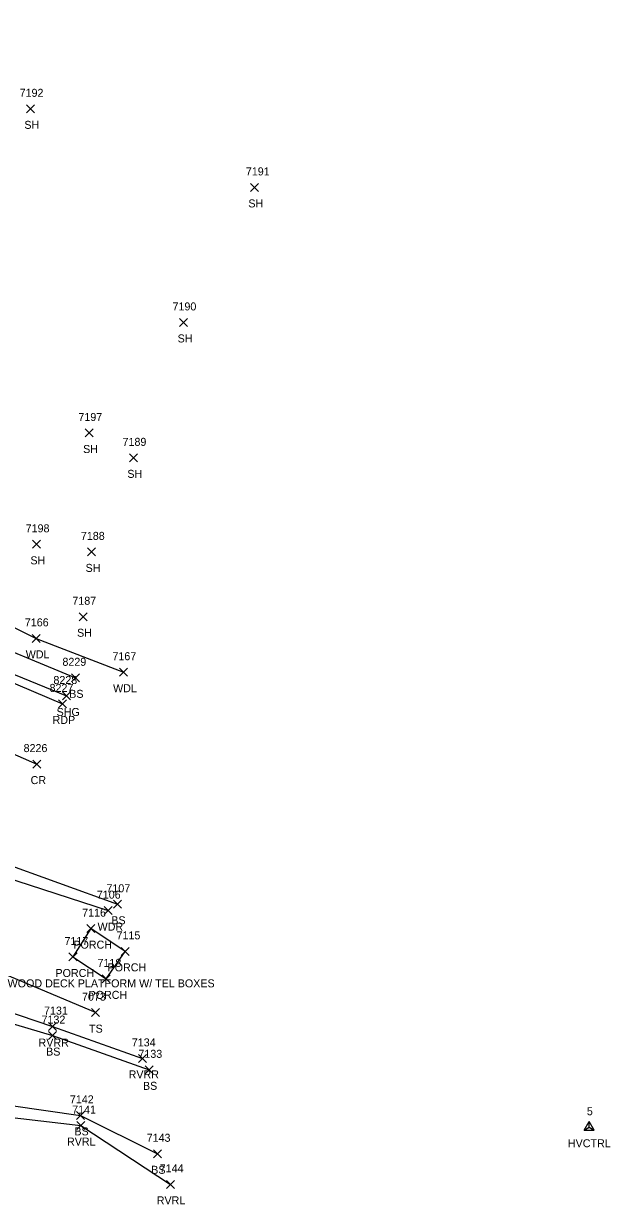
# Model space of a CAD drawing. Extents: x 1588028 to 1589597, y 137576 to 138176.
# Drawn here: x 1589450 to 1589596.6, y 137576.4 to 137871.5 of the extents above; entities that cross this region are included whole.
import ezdxf

# ---------------------------------------------------------------- set-up
doc = ezdxf.new("R2010")
doc.units = 0
for name, color, linetype in [('C_A', 7, 'Continuous'), ('C_I', 7, 'Continuous'), ('CPSM', 7, 'Continuous'), ('L_A', 7, 'Continuous'), ('L_C', 7, 'Continuous'), ('L_I', 7, 'Continuous'), ('L_TIC', 7, 'Continuous'), ('LAWA', 7, 'Continuous'), ('LAWE', 7, 'Continuous'), ('LBF', 7, 'Continuous'), ('LELB', 7, 'Continuous'), ('P_A', 7, 'Continuous'), ('P_I', 7, 'Continuous'), ('P_TIC', 7, 'Continuous'), ('PET', 7, 'Continuous'), ('PRC', 7, 'Continuous'), ('PSU', 7, 'Continuous')]:
    doc.layers.add(name, color=color, linetype=linetype)

msp = doc.modelspace()

# ---------------------------------------------------------------- linework, layer by layer
at = {"layer": 'CPSM'}
for p, q in [((1589590.03, 137594.95), (1589591.28, 137597.12)), ((1589590.03, 137594.95), (1589591.28, 137595.67)), ((1589590.03, 137594.95), (1589592.53, 137594.95)), ((1589592.53, 137594.95), (1589591.28, 137597.12)), ((1589591.28, 137595.67), (1589591.28, 137597.12)), ((1589591.28, 137595.67), (1589591.28, 137595.67)), ((1589591.28, 137595.67), (1589592.53, 137594.95))]:
    msp.add_line(p, q, dxfattribs=at)
at = {"layer": 'L_TIC'}
for points in [[(1589450.71, 137849.18), (1589452.71, 137851.18)], [(1589452.71, 137849.18), (1589450.71, 137851.18)], [(1589506.66, 137829.53), (1589508.66, 137831.53)], [(1589508.66, 137829.53), (1589506.66, 137831.53)], [(1589488.99, 137795.79), (1589490.99, 137797.79)], [(1589490.99, 137795.79), (1589488.99, 137797.79)], [(1589465.39, 137768.16), (1589467.39, 137770.16)], [(1589467.39, 137768.16), (1589465.39, 137770.16)], [(1589476.43, 137761.95), (1589478.43, 137763.95)], [(1589478.43, 137761.95), (1589476.43, 137763.95)], [(1589452.22, 137740.34), (1589454.22, 137742.34)], [(1589454.22, 137740.34), (1589452.22, 137742.34)], [(1589466.01, 137738.45), (1589468.01, 137740.45)], [(1589468.01, 137738.45), (1589466.01, 137740.45)], [(1589463.89, 137722.24), (1589465.89, 137724.24)], [(1589465.89, 137722.24), (1589463.89, 137724.24)], [(1589452.12, 137716.84), (1589454.12, 137718.84)], [(1589454.12, 137716.84), (1589452.12, 137718.84)], [(1589473.94, 137708.38), (1589475.94, 137710.38)], [(1589475.94, 137708.38), (1589473.94, 137710.38)], [(1589461.97, 137706.98), (1589463.97, 137708.98)], [(1589463.97, 137706.98), (1589461.97, 137708.98)], [(1589472.48, 137650.39), (1589474.48, 137652.39)], [(1589474.48, 137650.39), (1589472.48, 137652.39)], [(1589470.13, 137648.8), (1589472.13, 137650.8)], [(1589472.13, 137648.8), (1589470.13, 137650.8)], [(1589465.82, 137644.3), (1589467.82, 137646.3)], [(1589467.82, 137644.3), (1589465.82, 137646.3)], [(1589461.35, 137637.22), (1589463.35, 137639.22)], [(1589463.35, 137637.22), (1589461.35, 137639.22)], [(1589474.36, 137638.63), (1589476.36, 137640.63)], [(1589476.36, 137638.63), (1589474.36, 137640.63)], [(1589469.61, 137631.75), (1589471.61, 137633.75)], [(1589471.61, 137631.75), (1589469.61, 137633.75)], [(1589466.95, 137623.31), (1589468.95, 137625.31)], [(1589468.95, 137623.31), (1589466.95, 137625.31)], [(1589456.23, 137619.82), (1589458.23, 137621.82)], [(1589458.23, 137619.82), (1589456.23, 137621.82)], [(1589456.19, 137617.58), (1589458.19, 137619.58)], [(1589458.19, 137617.58), (1589456.19, 137619.58)], [(1589478.74, 137611.88), (1589480.74, 137613.88)], [(1589480.74, 137611.88), (1589478.74, 137613.88)], [(1589480.39, 137609.02), (1589482.39, 137611.02)], [(1589482.39, 137609.02), (1589480.39, 137611.02)], [(1589463.26, 137597.64), (1589465.26, 137599.64)], [(1589465.26, 137597.64), (1589463.26, 137599.64)], [(1589463.28, 137595.09), (1589465.28, 137597.09)], [(1589465.28, 137595.09), (1589463.28, 137597.09)], [(1589482.45, 137588.04), (1589484.45, 137590.04)], [(1589484.45, 137588.04), (1589482.45, 137590.04)], [(1589485.71, 137580.4), (1589487.71, 137582.4)], [(1589487.71, 137580.4), (1589485.71, 137582.4)]]:
    msp.add_lwpolyline(points, dxfattribs=at)
at = {"layer": 'LAWA'}
for points in [[(1589191.48, 137827.66), (1589208.47, 137821.19), (1589231.01, 137810.22), (1589260.79, 137799.99), (1589288.54, 137790.36), (1589312.49, 137778.55), (1589337.68, 137767.31), (1589356.85, 137760.89), (1589388.23, 137746.7), (1589420.91, 137733.88), (1589453.12, 137717.84), (1589474.94, 137709.38)], [(1589349.24, 137689.61), (1589382.22, 137681.05), (1589414.78, 137667.9), (1589444.95, 137658.35), (1589471.13, 137649.8)]]:
    msp.add_lwpolyline(points, dxfattribs=at)
at = {"layer": 'LAWE'}
for points in [[(1588998.37, 137781.01), (1589022.99, 137780.11), (1589053.11, 137769.29), (1589085.17, 137761.52), (1589118.32, 137748.59), (1589139.23, 137719.4), (1589162.49, 137704.02), (1589194.14, 137678.84), (1589218.55, 137662.87), (1589237.06, 137655.88), (1589274.24, 137640.2), (1589299.98, 137630.61), (1589325.3, 137627.35), (1589364.55, 137614.89), (1589400.15, 137603.63), (1589430.64, 137600.05), (1589464.28, 137596.09), (1589486.71, 137581.4)], [(1589165.8, 137734.64), (1589187.94, 137715.26), (1589212.73, 137704.5), (1589228.51, 137693.02), (1589244.33, 137677.06), (1589269.62, 137665.25), (1589295.65, 137657.92), (1589324.97, 137652.81), (1589365.32, 137641.86), (1589399.41, 137634.7), (1589423.88, 137632.18), (1589457.23, 137620.82), (1589479.74, 137612.88)]]:
    msp.add_lwpolyline(points, dxfattribs=at)
at = {"layer": 'LBF'}
for points in [[(1589475.36, 137639.63), (1589466.82, 137645.3), (1589462.35, 137638.22), (1589470.61, 137632.75)], [(1589470.61, 137632.75), (1589475.36, 137639.63)]]:
    msp.add_lwpolyline(points, dxfattribs=at)
at = {"layer": 'LELB'}
for points in [[(1588992.54, 137792.39), (1589023.3, 137782.03), (1589052.1, 137771.44), (1589084.42, 137763.28), (1589121.54, 137752.14), (1589143.04, 137720.61), (1589163.05, 137704.95), (1589194.58, 137680.14), (1589220, 137665.12), (1589237.76, 137657.31), (1589273.63, 137642.37), (1589300.04, 137631.76), (1589324.52, 137628.67), (1589366.23, 137617.74), (1589400.05, 137606.05), (1589430.12, 137603.56), (1589464.26, 137598.64), (1589483.45, 137589.04)], [(1589357.82, 137751.59), (1589375.51, 137744.43), (1589404.41, 137733.04), (1589436.02, 137719.14), (1589462.97, 137707.98)], [(1589467.95, 137624.31), (1589440.56, 137635.88), (1589398.74, 137645.95), (1589371.69, 137651.72), (1589343.02, 137657.2), (1589343.09, 137676.77), (1589344.49, 137692.63)], [(1589349.04, 137693.04), (1589381.83, 137683.89), (1589416.13, 137670.61), (1589443.9, 137662.06), (1589473.48, 137651.39)], [(1589327.62, 137649.4), (1589364.6, 137640.66), (1589399.91, 137633.14), (1589424.96, 137628.14), (1589457.19, 137618.58), (1589481.39, 137610.02)]]:
    msp.add_lwpolyline(points, dxfattribs=at)
at = {"layer": 'P_TIC'}
for points in [[(1589459.72, 137702.44), (1589461.72, 137704.44)], [(1589461.72, 137702.44), (1589459.72, 137704.44)], [(1589458.76, 137700.46), (1589460.76, 137702.46)], [(1589460.76, 137700.46), (1589458.76, 137702.46)], [(1589452.33, 137685.42), (1589454.33, 137687.42)], [(1589454.33, 137685.42), (1589452.33, 137687.42)]]:
    msp.add_lwpolyline(points, dxfattribs=at)
at = {"layer": 'PET'}
msp.add_lwpolyline([(1588976.42, 137837.98), (1588964.71, 137855.4), (1588953.74, 137871.46), (1588980.82, 137866.91), (1589021.21, 137859.55), (1589054.58, 137852.92), (1589087.36, 137843.77), (1589127.64, 137831.45), (1589150.05, 137824.37), (1589196.14, 137808.72), (1589243.87, 137790.96), (1589276.87, 137778.08), (1589322.25, 137759.62), (1589367.82, 137740.82), (1589401.87, 137726.11), (1589432.81, 137712.85), (1589459.76, 137701.46)], dxfattribs=at)
at = {"layer": 'PRC'}
msp.add_lwpolyline([(1588964.71, 137855.4), (1588980.14, 137852.51), (1589018.19, 137844.35), (1589051.57, 137836.27), (1589092.27, 137825.07), (1589122.68, 137816.23), (1589170.7, 137800.29), (1589190.72, 137793.38), (1589238.44, 137775.62), (1589271.31, 137762.4), (1589315.94, 137744.35), (1589366.22, 137723.58), (1589395.71, 137710.87), (1589428.18, 137697.42), (1589453.33, 137686.42)], dxfattribs=at)
at = {"layer": 'PSU'}
msp.add_lwpolyline([(1589152.74, 137827.96), (1589197.07, 137811.88), (1589244.81, 137793.79), (1589277.33, 137781.11), (1589323.36, 137762.65), (1589353.23, 137749.52), (1589368.68, 137743.62), (1589402.84, 137728.77), (1589433.2, 137714.7), (1589460.72, 137703.44)], dxfattribs=at)

# ---------------------------------------------------------------- texts
at = {"layer": 'C_A'}
msp.add_text('HVCTRL', height=2, dxfattribs=at).set_placement((1589585.97, 137590.67))
at = {"layer": 'C_I'}
msp.add_text('5', height=2, dxfattribs=at).set_placement((1589590.71, 137598.67))
at = {"layer": 'L_A'}
for s, p in [('SH', (1589450.2, 137845.17)), ('SH', (1589506.15, 137825.53)), ('SH', (1589488.48, 137791.79)), ('SH', (1589464.88, 137764.16)), ('SH', (1589475.92, 137757.95)), ('SH', (1589451.71, 137736.34)), ('SH', (1589465.5, 137734.45)), ('SH', (1589463.37, 137718.24)), ('WDL', (1589450.54, 137712.84)), ('BS', (1589461.41, 137702.98)), ('WDL', (1589472.36, 137704.38)), ('BS', (1589471.92, 137646.39)), ('WDR', (1589468.49, 137644.8)), ('PORCH', (1589462.44, 137640.3)), ('PORCH', (1589470.98, 137634.63)), ('PORCH', (1589457.97, 137633.22)), ('PORCH', (1589466.23, 137627.75)), ('TS', (1589466.36, 137619.31)), ('RVRR', (1589453.74, 137615.82)), ('BS', (1589455.63, 137613.58)), ('RVRR', (1589476.25, 137607.88)), ('BS', (1589479.83, 137605.02)), ('BS', (1589462.7, 137593.64)), ('RVRL', (1589460.85, 137591.09)), ('BS', (1589481.89, 137584.04)), ('RVRL', (1589483.27, 137576.4))]:
    msp.add_text(s, height=2, dxfattribs=at).set_placement(p)
at = {"layer": 'L_C'}
msp.add_text('WOOD DECK PLATFORM W/ TEL BOXES', height=2, dxfattribs=at).set_placement((1589446.02, 137630.63))
at = {"layer": 'L_I'}
for s, p in [('7192', (1589449.02, 137853.17)), ('7191', (1589505.53, 137833.53)), ('7190', (1589487.21, 137799.79)), ('7197', (1589463.7, 137772.16)), ('7189', (1589474.73, 137765.95)), ('7198', (1589450.53, 137744.34)), ('7188', (1589464.32, 137742.45)), ('7187', (1589462.19, 137726.24)), ('7166', (1589450.32, 137720.84)), ('8229', (1589459.71, 137710.98)), ('7167', (1589472.2, 137712.38)), ('7106', (1589468.3, 137652.8)), ('7107', (1589470.7, 137654.39)), ('7116', (1589464.64, 137648.3)), ('7117', (1589460.23, 137641.22)), ('7115', (1589473.23, 137642.63)), ('7118', (1589468.48, 137635.75)), ('7073', (1589464.61, 137627.31)), ('7131', (1589455.11, 137623.82)), ('7132', (1589454.49, 137621.58)), ('7134', (1589477.04, 137615.88)), ('7133', (1589478.69, 137613.02)), ('7142', (1589461.57, 137601.64)), ('7141', (1589462.15, 137599.09)), ('7143', (1589480.75, 137592.04)), ('7144', (1589484.01, 137584.4))]:
    msp.add_text(s, height=2, dxfattribs=at).set_placement(p)
at = {"layer": 'P_A'}
for s, p in [('RDP', (1589457.25, 137696.46)), ('SHG', (1589458.25, 137698.44)), ('CR', (1589451.76, 137681.42))]:
    msp.add_text(s, height=2, dxfattribs=at).set_placement(p)
at = {"layer": 'P_I'}
for s, p in [('8228', (1589457.46, 137706.44)), ('8227', (1589456.5, 137704.46)), ('8226', (1589450.01, 137689.42))]:
    msp.add_text(s, height=2, dxfattribs=at).set_placement(p)

doc.saveas('drawing.dxf')
